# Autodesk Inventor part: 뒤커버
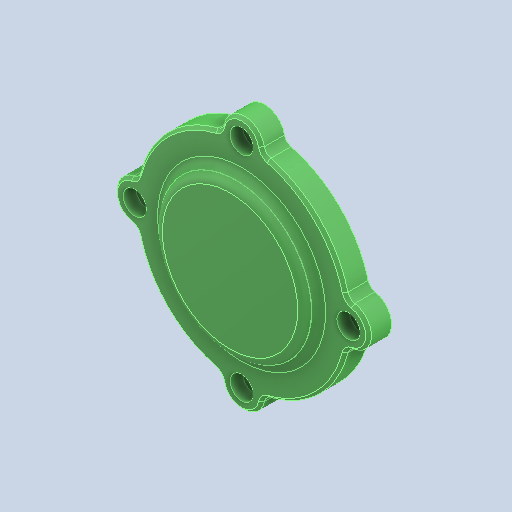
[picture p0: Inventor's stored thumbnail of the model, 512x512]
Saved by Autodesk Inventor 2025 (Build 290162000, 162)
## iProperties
Created: 2025-08
Part Number: 뒤커버
Material: 알루미늄 6061
Document SubType Name: Modeling
Designer: infra04
Density: 2.71 g/cm^3
Appearance: 기본값
Company: 한국ATC센터
Author: jhkim
Sending System: Autodesk Inventor 2026
Preprocessor: ST-DEVELOPER v20.1
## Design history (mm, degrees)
feature "솔리드1"
node "솔리드2"
